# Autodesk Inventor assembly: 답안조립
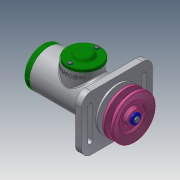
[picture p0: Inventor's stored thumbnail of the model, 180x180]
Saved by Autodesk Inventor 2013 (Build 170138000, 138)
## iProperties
Created: 2021-07
Part Number: 답안조립
Document SubType Name: Assembly
Designer: 19
Author: 19
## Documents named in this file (20)
- C:\Users\user\Desktop\710706V1014\답안조립.iam
- C:\Users\user\Desktop\710706V1014\본체.ipt
- C:\Users\user\Desktop\710706V1014\V-벨트풀리.ipt
- C:\Users\user\Desktop\710706V1014\너트 M10.ipt
- C:\Users\user\Desktop\710706V1014\멈춤링 15 x 1.ipt
- C:\Users\user\Desktop\710706V1014\멈춤링 35 x 1.6.ipt
- C:\Users\user\Desktop\710706V1014\베어링 15 x 35 x 11.ipt
- C:\Users\user\Desktop\710706V1014\볼트 M4 x 10.ipt
- C:\Users\user\Desktop\710706V1014\부시1.ipt
- C:\Users\user\Desktop\710706V1014\부시2.ipt
- C:\Users\user\Desktop\710706V1014\사이드 커버.ipt
- 사이드 커버.ipt
- C:\Users\user\Desktop\710706V1014\십자볼트 M3 x 10.ipt
- C:\Users\user\Desktop\710706V1014\오일 실 15 25 7.ipt
- C:\Users\user\Desktop\710706V1014\와셔 3 x 6.ipt
- C:\Users\user\Desktop\710706V1014\와셔 4 x 16.ipt
- C:\Users\user\Desktop\710706V1014\와셔 10 x 21.ipt
- C:\Users\user\Desktop\710706V1014\축.ipt
- C:\Users\user\Desktop\710706V1014\키 4 x 4 x 18.ipt
- C:\Users\user\Desktop\710706V1014\탑 커버.ipt
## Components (2 placed, 2 different names)
1. V-벨트풀리:1
2. ISO 4017 M4 x 10:1
